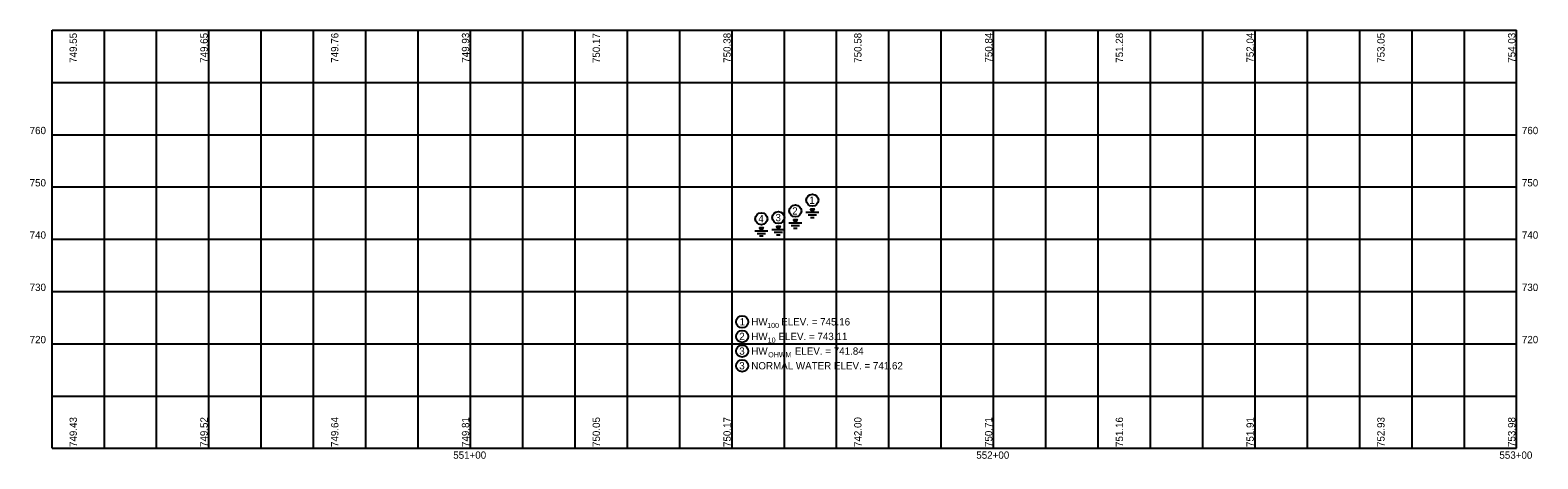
# Model space of a CAD drawing. Extents: x 411 to 699, y 698 to 780.
import ezdxf

# ---------------------------------------------------------------- set-up
doc = ezdxf.new("R2010")
doc.units = 0
for name, color, linetype in [('GT_Project_Cells', 7, 'Continuous'), ('GT_Project_Soil_Boring', 7, 'Continuous'), ('GT_Project_Text', 7, 'Continuous'), ('SC_Scratch5', 7, 'Continuous'), ('SC_Scratch6', 7, 'Continuous')]:
    doc.layers.add(name, color=color, linetype=linetype)

msp = doc.modelspace()

# ---------------------------------------------------------------- linework, layer by layer
at = {"layer": 'GT_Project_Cells'}
for p, q in [((414.86, 780), (694.86, 780)), ((414.86, 700), (414.86, 780)), ((414.86, 700), (414.86, 780)), ((424.86, 700), (424.86, 780)), ((434.86, 700), (434.86, 780)), ((444.86, 700), (444.86, 780)), ((454.86, 700), (454.86, 780)), ((464.86, 700), (464.86, 780)), ((474.86, 700), (474.86, 780)), ((484.86, 700), (484.86, 780)), ((494.86, 700), (494.86, 780)), ((504.86, 700), (504.86, 780)), ((514.86, 700), (514.86, 780)), ((524.86, 700), (524.86, 780)), ((534.86, 700), (534.86, 780)), ((544.86, 700), (544.86, 780)), ((554.86, 700), (554.86, 780)), ((564.86, 700), (564.86, 780)), ((574.86, 700), (574.86, 780)), ((584.86, 700), (584.86, 780)), ((594.86, 700), (594.86, 780)), ((604.86, 700), (604.86, 780)), ((614.86, 700), (614.86, 780)), ((624.86, 700), (624.86, 780)), ((634.86, 700), (634.86, 780)), ((644.86, 700), (644.86, 780)), ((654.86, 700), (654.86, 780)), ((664.86, 700), (664.86, 780)), ((674.86, 700), (674.86, 780)), ((684.86, 700), (684.86, 780)), ((694.86, 700), (694.86, 780)), ((414.86, 770), (694.86, 770)), ((414.86, 760), (694.86, 760)), ((414.86, 750), (694.86, 750)), ((414.86, 740), (694.86, 740)), ((414.86, 730), (694.86, 730)), ((414.86, 720), (694.86, 720)), ((414.86, 710), (694.86, 710)), ((414.86, 700), (694.86, 700))]:
    msp.add_line(p, q, dxfattribs=at)
at = {"layer": 'GT_Project_Soil_Boring'}
for p, q in [((558.96, 745.16), (561.46, 745.16)), ((558.96, 745.16), (561.46, 745.16)), ((559.4, 744.66), (561.01, 744.66)), ((559.85, 744.16), (560.56, 744.16)), ((549.21, 741.62), (551.71, 741.62)), ((549.65, 741.12), (551.26, 741.12)), ((552.46, 741.84), (554.96, 741.84)), ((552.9, 741.34), (554.51, 741.34)), ((553.35, 740.84), (554.06, 740.84)), ((555.71, 743.11), (558.21, 743.11)), ((556.15, 742.61), (557.76, 742.61)), ((556.6, 742.11), (557.31, 742.11)), ((550.1, 740.62), (550.81, 740.62))]:
    msp.add_line(p, q, dxfattribs=at)
for points in [[(556.58, 743.76), (557.33, 743.76), (556.96, 743.11)], [(559.83, 745.81), (560.58, 745.81), (560.21, 745.16)], [(559.83, 745.81), (560.58, 745.81), (560.21, 745.16)], [(550.08, 742.27), (550.83, 742.27), (550.46, 741.62)], [(553.33, 742.49), (554.08, 742.49), (553.71, 741.84)]]:
    msp.add_lwpolyline(points, close=True, dxfattribs=at)
for centre in [(556.96, 745.41), (560.21, 747.46), (550.46, 743.92), (553.71, 744.14), (546.79, 724.2), (546.79, 721.4), (546.79, 718.6), (546.79, 715.8)]:
    msp.add_circle(centre, 1.15, dxfattribs=at)

# ---------------------------------------------------------------- texts
for s, p in [('1', (559.63, 746.76)), ('4', (549.88, 743.22)), ('3', (553.16, 743.44)), ('2', (556.36, 744.71))]:
    msp.add_text(s, height=1.4, rotation=360, dxfattribs=at).set_placement(p)
for s, height, p in [('1', 1.4, (546.32, 723.5)), ('HW     ELEV. = 745.16', 1.4, (548.54, 723.5)), ('100', 0.983, (551.58, 723.01)), ('2', 1.4, (546.24, 720.7)), ('HW    ELEV. = 743.11', 1.4, (548.54, 720.7)), ('10', 0.983, (551.67, 720.21)), ('3', 1.4, (546.24, 717.9)), ('HW          ELEV. = 741.84', 1.4, (548.54, 717.9)), ('OHWM', 0.983, (551.76, 717.41)), ('3', 1.4, (546.24, 715.1)), ('NORMAL WATER ELEV. = 741.62', 1.4, (548.54, 715.1))]:
    msp.add_text(s, height=height, dxfattribs=at).set_placement(p)
at = {"layer": 'GT_Project_Text'}
for s, p in [('760', (410.58, 760.1)), ('760', (695.86, 760.1)), ('750', (410.58, 750.1)), ('750', (695.86, 750.1)), ('740', (410.58, 740.1)), ('740', (695.86, 740.1)), ('730', (410.58, 730.1)), ('730', (695.86, 730.1)), ('720', (410.58, 720.1)), ('720', (695.86, 720.1)), ('551+00', (491.56, 698)), ('552+00', (591.56, 698)), ('553+00', (691.56, 698))]:
    msp.add_text(s, height=1.4, dxfattribs=at).set_placement(p)
at = {"layer": 'SC_Scratch5'}
for s, p in [('749.43', (419.61, 700.25)), ('749.52', (444.61, 700.25)), ('749.64', (469.61, 700.25)), ('749.81', (494.61, 700.25)), ('750.05', (519.61, 700.25)), ('750.17', (544.61, 700.25)), ('742.00', (569.61, 700.25)), ('750.71', (594.61, 700.25)), ('751.16', (619.61, 700.25)), ('751.91', (644.61, 700.25)), ('752.93', (669.61, 700.25)), ('753.98', (694.61, 700.25))]:
    msp.add_text(s, height=1.4, rotation=90, dxfattribs=at).set_placement(p)
at = {"layer": 'SC_Scratch6'}
for s, p in [('749.55', (419.61, 773.74)), ('749.65', (444.61, 773.74)), ('749.76', (469.61, 773.75)), ('749.93', (494.61, 773.77)), ('750.17', (519.61, 773.69)), ('750.38', (544.61, 773.75)), ('750.58', (569.61, 773.75)), ('750.84', (594.61, 773.79)), ('751.28', (619.61, 773.75)), ('752.04', (644.61, 773.79)), ('753.05', (669.61, 773.74)), ('754.03', (694.61, 773.77))]:
    msp.add_text(s, height=1.4, rotation=90, dxfattribs=at).set_placement(p)

doc.saveas('drawing.dxf')
